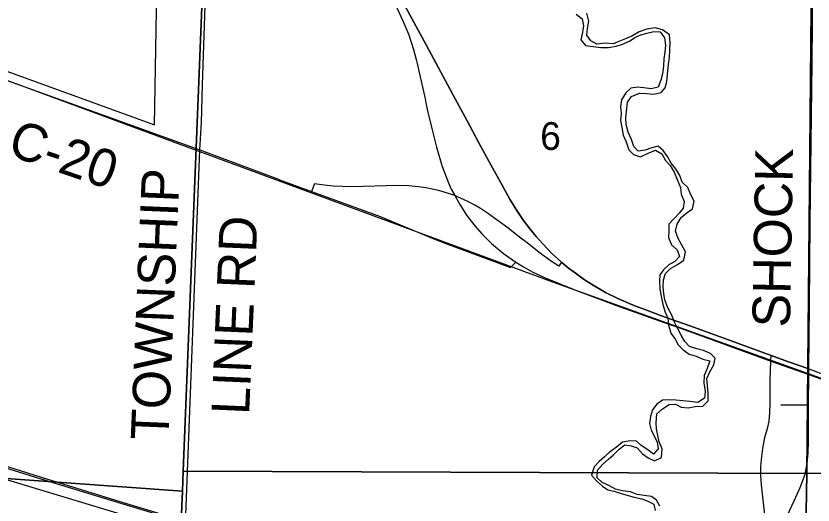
# Model space of a CAD drawing. Extents: x 0 to 34, y 0 to 22.
# Drawn here: x 25.81 to 27.011, y 18.872 to 19.609 of the extents above; entities that cross this region are included whole.
import ezdxf

# ---------------------------------------------------------------- set-up
doc = ezdxf.new("R2010")
doc.units = 0
for name, color, linetype in [('GM_X_City_Street', 7, 'Continuous'), ('GM_X_County_Road', 7, 'Continuous'), ('GM_X_County_Road_Text', 7, 'Continuous'), ('GM_X_Interchange_Ramps', 7, 'Continuous'), ('GM_X_Minor_River', 7, 'Continuous'), ('GM_X_Rail_Line', 7, 'Continuous'), ('GM_X_Section', 7, 'Continuous'), ('GM_X_Section_Text', 7, 'Continuous'), ('GM_X_State_Route', 7, 'Continuous'), ('GM_X_Township_Road', 7, 'Continuous'), ('GM_X_Township_Road_Text', 7, 'Continuous'), ('GM_X_US_Route', 7, 'Continuous')]:
    doc.layers.add(name, color=color, linetype=linetype)

msp = doc.modelspace()

# ---------------------------------------------------------------- linework, layer by layer
at = {"layer": 'GM_X_City_Street'}
msp.add_lwpolyline([(25.7608, 19.5385), (26.0181, 19.4449), (26.0246, 19.8182), (26.0322, 19.818), (26.0322, 20.0343), (26.0952, 20.0332), (26.0952, 20.0736), (25.9699, 20.3158)], dxfattribs=at)
at = {"layer": 'GM_X_County_Road'}
msp.add_line((26.0643, 18.8283), (26.0866, 19.4072), dxfattribs=at)
for points in [[(26.0866, 19.4072), (26.089, 19.4486), (26.0905, 19.5054), (26.0945, 19.6244), (26.0989, 19.7481), (26.1013, 19.8177), (26.1022, 19.82)], [(25.5658, 19.595), (25.7402, 19.5316), (26.0796, 19.4097), (26.0866, 19.4072)], [(26.0866, 19.4072), (26.2051, 19.3627), (26.2079, 19.3616)], [(26.2079, 19.3616), (26.2548, 19.3444), (26.2743, 19.3373)], [(26.2743, 19.3373), (26.3581, 19.3069), (26.4391, 19.2729)]]:
    msp.add_lwpolyline(points, dxfattribs=at)
at = {"layer": 'GM_X_Interchange_Ramps'}
for points in [[(26.5704, 19.2741), (26.5614, 19.281), (26.5508, 19.2894), (26.5291, 19.3051), (26.5214, 19.3106), (26.5095, 19.3185), (26.5008, 19.3238), (26.4916, 19.3287), (26.474, 19.337), (26.4706, 19.3385), (26.4468, 19.3457), (26.4368, 19.3481), (26.4271, 19.35), (26.4159, 19.3516), (26.4013, 19.3528), (26.3849, 19.3532), (26.3673, 19.3531), (26.3326, 19.3517), (26.3133, 19.3515), (26.3023, 19.3517), (26.2877, 19.3526), (26.2741, 19.3539), (26.2592, 19.356), (26.2548, 19.3444)], [(26.4391, 19.2729), (26.4572, 19.2658), (26.5548, 19.2296), (26.5627, 19.2378)], [(26.6317, 19.2379), (26.6274, 19.2318), (26.6167, 19.2389), (26.6, 19.2511), (26.5778, 19.2685), (26.5704, 19.2741)]]:
    msp.add_lwpolyline(points, dxfattribs=at)
at = {"layer": 'GM_X_Minor_River'}
for points in [[(26.6536, 19.6116), (26.6629, 19.6049), (26.6649, 19.5942), (26.6631, 19.5844), (26.6609, 19.5731), (26.6679, 19.5645), (26.6792, 19.5631), (26.6906, 19.5612), (26.7023, 19.5613), (26.7141, 19.5636), (26.7233, 19.5664), (26.7341, 19.571), (26.7418, 19.5765), (26.751, 19.5804), (26.7602, 19.5832), (26.7705, 19.5856), (26.7803, 19.585), (26.7869, 19.576), (26.7881, 19.565), (26.7871, 19.5544), (26.7857, 19.5446), (26.7854, 19.5332), (26.7835, 19.5215), (26.7814, 19.512), (26.7773, 19.5015), (26.7666, 19.4991), (26.7557, 19.5006), (26.7458, 19.5016), (26.7359, 19.5), (26.7285, 19.493), (26.7218, 19.4825), (26.7204, 19.4719), (26.7213, 19.462), (26.7206, 19.4514), (26.7222, 19.4408), (26.7245, 19.4293), (26.7292, 19.4193), (26.733, 19.407), (26.7401, 19.4), (26.7506, 19.3967), (26.761, 19.4017), (26.7732, 19.4067), (26.7829, 19.4011), (26.788, 19.3911), (26.7953, 19.3833), (26.8015, 19.3736), (26.8058, 19.3625), (26.8108, 19.3502), (26.8116, 19.3403), (26.8166, 19.3292), (26.8148, 19.319), (26.8086, 19.3116), (26.8012, 19.3038), (26.7933, 19.2949), (26.7931, 19.2854), (26.7928, 19.2748), (26.7974, 19.264), (26.8056, 19.2562)], [(26.8226, 19.0184), (26.8329, 19.0201), (26.8443, 19.0209), (26.8525, 19.029), (26.8524, 19.0404), (26.8516, 19.0514), (26.8507, 19.0625), (26.8552, 19.0726), (26.8612, 19.0831), (26.863, 19.0933), (26.8559, 19.0999), (26.8454, 19.1048), (26.8356, 19.1069), (26.8244, 19.1107), (26.8174, 19.1184), (26.8116, 19.1277), (26.8069, 19.1373), (26.8019, 19.1473), (26.7972, 19.1589), (26.7918, 19.1689), (26.7872, 19.1812), (26.7856, 19.1907), (26.7847, 19.2002), (26.785, 19.2112), (26.7883, 19.2206), (26.7957, 19.2284), (26.8065, 19.2345), (26.8161, 19.2407), (26.8184, 19.2536), (26.813, 19.2636), (26.8072, 19.2733), (26.8033, 19.2844), (26.8058, 19.2949), (26.8118, 19.305), (26.8207, 19.3127), (26.8289, 19.3182), (26.8314, 19.3299), (26.8264, 19.3395), (26.8221, 19.3503), (26.8136, 19.3585), (26.8097, 19.3685), (26.8036, 19.3785), (26.797, 19.3871), (26.7912, 19.3971), (26.7846, 19.406), (26.7772, 19.4127), (26.7676, 19.4103), (26.7577, 19.4067), (26.747, 19.4051), (26.7404, 19.4122), (26.7369, 19.4229), (26.7319, 19.4337), (26.7291, 19.4455), (26.7283, 19.4558), (26.7302, 19.469), (26.7312, 19.4789), (26.7371, 19.4874), (26.749, 19.4928), (26.7596, 19.4921), (26.7706, 19.4911), (26.7816, 19.4934), (26.7875, 19.5008), (26.7901, 19.5103), (26.7915, 19.5209), (26.7927, 19.5364), (26.7941, 19.5462), (26.7947, 19.5572), (26.7951, 19.5686), (26.7942, 19.5804), (26.7838, 19.5879), (26.7729, 19.5909), (26.76, 19.5893), (26.7485, 19.5851), (26.7377, 19.5785), (26.7281, 19.5746), (26.7181, 19.5703), (26.7093, 19.5668), (26.6976, 19.5682), (26.685, 19.5667), (26.6757, 19.5715), (26.6698, 19.58), (26.6709, 19.5899), (26.6727, 19.6012), (26.6696, 19.6131)], [(26.8056, 19.2562), (26.8095, 19.2462), (26.8021, 19.2388), (26.7932, 19.2338), (26.785, 19.2264), (26.7795, 19.2186), (26.7793, 19.2091), (26.7797, 19.1969), (26.7817, 19.1866), (26.784, 19.174), (26.7879, 19.1625), (26.7918, 19.1537), (26.793, 19.143), (26.7961, 19.1308), (26.8027, 19.1219), (26.8074, 19.1134), (26.8151, 19.1056), (26.824, 19.0989), (26.8346, 19.0959), (26.8443, 19.0915), (26.8549, 19.0889), (26.8508, 19.0777), (26.8467, 19.0668), (26.846, 19.0561), (26.8479, 19.0428), (26.8469, 19.0326), (26.8372, 19.026), (26.8248, 19.0279), (26.8146, 19.0289), (26.804, 19.0296), (26.7934, 19.0303), (26.7839, 19.0298), (26.775, 19.0235), (26.7687, 19.015), (26.7654, 19.0052), (26.764, 18.9946), (26.7667, 18.9847), (26.771, 18.9758), (26.7757, 18.9662), (26.777, 18.9563), (26.7703, 18.9485), (26.7617, 18.9548), (26.7517, 18.9612), (26.7447, 18.9678), (26.7352, 18.9684), (26.7234, 18.9665), (26.7145, 18.9588), (26.7036, 18.9507), (26.6962, 18.9445), (26.6881, 18.9375), (26.6807, 18.9293), (26.6769, 18.9165), (26.6843, 18.908), (26.6931, 18.9001), (26.7013, 18.8946), (26.7108, 18.8924), (26.7213, 18.8891), (26.7318, 18.8858), (26.7412, 18.8836), (26.7525, 18.881), (26.7616, 18.8777), (26.7705, 18.8729), (26.7725, 18.8634)], [(26.7754, 19.0091), (26.7839, 19.0165), (26.7936, 19.023), (26.8031, 19.0239), (26.812, 19.0191), (26.8226, 19.0184)], [(26.7799, 18.87), (26.7749, 18.8789), (26.767, 18.8844), (26.7561, 18.8859), (26.7455, 18.8873), (26.7354, 18.8914), (26.7233, 18.8932), (26.7131, 18.8958), (26.703, 18.901), (26.6929, 18.9058), (26.6852, 18.9129), (26.6858, 18.9242), (26.694, 18.9331), (26.7022, 18.9409), (26.71, 18.9475), (26.7186, 18.956), (26.7271, 18.9622), (26.7365, 18.9608), (26.7455, 18.9579), (26.7536, 18.949), (26.7622, 18.943), (26.7719, 18.9382), (26.7823, 18.9432), (26.7834, 18.9565), (26.7788, 18.9669), (26.7767, 18.9764), (26.7747, 18.9863), (26.7742, 18.9958), (26.7754, 19.0091)]]:
    msp.add_lwpolyline(points, dxfattribs=at)
at = {"layer": 'GM_X_Rail_Line'}
for points in [[(24.6857, 19.9193), (25.0148, 19.7985), (25.4772, 19.6296), (26.0332, 19.4244), (26.618, 19.2083), (27.1754, 19.0083), (27.8265, 18.7785), (28.397, 18.5695), (29.2915, 18.2251), (29.5147, 18.1387)], [(24.1704, 19.5327), (24.2425, 19.4909), (24.3878, 19.4135), (24.5787, 19.3195), (24.7175, 19.2589), (24.8405, 19.2105), (24.9746, 19.1639), (25.4423, 19.0168), (26.3104, 18.7542), (27.1506, 18.4971), (27.9899, 18.2401), (28.4862, 18.088)], [(25.1011, 19.1396), (25.1536, 19.1235), (25.2694, 19.0879), (25.2996, 19.0787), (25.3683, 19.0577), (25.4595, 19.0299), (25.6015, 18.9867), (25.8055, 18.9242), (25.847, 18.9114), (25.9704, 18.8734), (26.0653, 18.8446), (26.2947, 18.7744), (26.4597, 18.7238), (26.5651, 18.6918), (26.6458, 18.6671), (26.7252, 18.6428), (26.8299, 18.611), (26.9128, 18.5857), (26.9875, 18.5627), (27.1965, 18.4991)], [(25.4438, 19.0347), (25.4601, 19.0321), (25.6021, 18.989), (25.8062, 18.9265), (25.8477, 18.9137), (25.9711, 18.8756), (26.066, 18.8468), (26.2954, 18.7766), (26.4604, 18.726), (26.5658, 18.694), (26.6465, 18.6693), (26.6813, 18.6587), (26.7055, 18.6488)]]:
    msp.add_lwpolyline(points, dxfattribs=at)
at = {"layer": 'GM_X_Section'}
for points in [[(28.0159, 19.8585), (28.001, 18.9217), (27.0012, 18.9192), (27.0095, 19.8363), (27.044, 19.8365)], [(25.0077, 19.8483), (25.0925, 19.8455), (26.0975, 19.8234), (26.0616, 18.9227), (26.0607, 18.8928), (24.9624, 18.9716)], [(27.0095, 19.8363), (27.0012, 18.9192), (26.0616, 18.9227), (26.0975, 19.8234)], [(26.0607, 18.8928), (26.0171, 17.9156), (26.0158, 17.891), (24.9267, 17.9117), (24.9624, 18.9716)], [(27.0012, 18.9192), (26.984, 17.9172), (26.0171, 17.9156), (26.0607, 18.8928), (26.0616, 18.9227)], [(28.001, 18.9217), (27.9928, 17.9132), (26.984, 17.9172), (27.0012, 18.9192)]]:
    msp.add_lwpolyline(points, close=True, dxfattribs=at)
at = {"layer": 'GM_X_State_Route'}
for points in [[(26.6317, 19.2379), (26.6172, 19.251), (26.6032, 19.2656), (26.5934, 19.2766), (26.5842, 19.2878), (26.5743, 19.3006), (26.5641, 19.3156), (26.5541, 19.3318), (26.5394, 19.3582), (26.5252, 19.3845), (26.5072, 19.4178), (26.4892, 19.4511), (26.4714, 19.4841), (26.4568, 19.5111), (26.4422, 19.5383), (26.4245, 19.571), (26.4065, 19.6043), (26.3883, 19.6381)], [(26.9477, 19.0971), (26.8819, 19.121), (26.8317, 19.1392), (26.7824, 19.157), (26.7611, 19.1649), (26.7396, 19.1731), (26.7174, 19.1826), (26.6977, 19.1923), (26.6792, 19.203), (26.6662, 19.2114), (26.6539, 19.2201), (26.6421, 19.229), (26.6317, 19.2379)], [(27.0042, 19.0768), (26.9737, 19.0877), (26.9477, 19.0971)], [(27.0041, 19.0684), (27.0041, 19.0714), (27.0042, 19.0768)], [(26.9651, 18.8414), (26.9822, 18.8778), (26.9912, 18.8979), (26.9985, 18.9182), (27.0019, 18.9342), (27.0031, 18.9504), (27.0037, 18.9675), (27.0038, 19.022), (27.0041, 19.0684)]]:
    msp.add_lwpolyline(points, dxfattribs=at)
at = {"layer": 'GM_X_Township_Road'}
msp.add_line((27.0038, 19.022), (26.9619, 19.0221), dxfattribs=at)
for points in [[(27.0042, 19.0768), (27.005, 19.173), (27.0061, 19.2969), (27.0091, 19.5392), (27.0117, 19.8339)], [(26.9438, 18.7976), (26.9401, 18.8386), (26.933, 18.9019), (26.9318, 18.9164), (26.9321, 18.9296), (26.9332, 18.9447), (26.9348, 18.9571), (26.938, 18.9733), (26.9426, 18.9888), (26.9445, 18.9983), (26.9455, 19.0107), (26.946, 19.0253), (26.9461, 19.0601), (26.9472, 19.0885), (26.9477, 19.0971)]]:
    msp.add_lwpolyline(points, dxfattribs=at)
at = {"layer": 'GM_X_US_Route'}
for points in [[(26.3883, 19.6381), (26.4065, 19.6043), (26.4245, 19.571), (26.4422, 19.5383), (26.4568, 19.5111), (26.4714, 19.4841), (26.4892, 19.4511), (26.5072, 19.4178), (26.5252, 19.3845), (26.5394, 19.3582), (26.5541, 19.3318), (26.5641, 19.3156), (26.5743, 19.3006), (26.5842, 19.2878), (26.5934, 19.2766), (26.6032, 19.2656), (26.6172, 19.251), (26.6317, 19.2379)], [(26.3777, 19.6323), (26.3839, 19.6203), (26.3926, 19.6017), (26.4013, 19.5806), (26.4087, 19.5583), (26.4127, 19.5433), (26.4141, 19.5374)], [(26.4141, 19.5374), (26.4161, 19.5285), (26.4225, 19.4996), (26.426, 19.484), (26.4272, 19.478)], [(26.4272, 19.478), (26.4297, 19.466), (26.4357, 19.4412), (26.4432, 19.4111), (26.4518, 19.3818), (26.4614, 19.3573), (26.4655, 19.3479), (26.4706, 19.3385), (26.4781, 19.3245), (26.4896, 19.3071), (26.5014, 19.292), (26.5114, 19.2807), (26.5261, 19.2661), (26.5439, 19.2509), (26.5627, 19.2378)], [(26.5627, 19.2378), (26.5742, 19.2306), (26.5883, 19.2229), (26.6051, 19.2151), (26.607, 19.2143)], [(26.6317, 19.2379), (26.6421, 19.229), (26.6539, 19.2201), (26.6662, 19.2114), (26.6792, 19.203), (26.6977, 19.1923), (26.7174, 19.1826), (26.7396, 19.1731), (26.7611, 19.1649), (26.7824, 19.157), (26.8317, 19.1392), (26.8819, 19.121), (26.9477, 19.0971)], [(26.607, 19.2143), (26.6564, 19.194), (26.692, 19.1808), (26.7129, 19.1732), (26.7863, 19.1468)], [(26.7863, 19.1468), (26.8121, 19.1376), (26.9472, 19.0885), (27.0041, 19.0684), (27.0497, 19.0517)], [(26.9477, 19.0971), (26.9737, 19.0877), (27.0042, 19.0768)], [(27.0042, 19.0768), (27.0338, 19.0659), (27.0763, 19.0506), (27.1619, 19.0197), (27.2046, 19.0042), (27.2509, 18.9877), (27.2902, 18.9738), (27.3459, 18.9544), (27.4319, 18.924), (27.4616, 18.9134), (27.4954, 18.9016)]]:
    msp.add_lwpolyline(points, dxfattribs=at)

# ---------------------------------------------------------------- texts
at = {"layer": 'GM_X_County_Road_Text'}
for s, rotation, p in [('C-20', 341.1304, (25.7946, 19.4002)), ('TOWNSHIP', 87.6083, (26.0392, 18.9687)), ('LINE RD', 87.541, (26.1608, 19.007))]:
    msp.add_text(s, height=0.05682, rotation=rotation, dxfattribs=at).set_placement(p)
at = {"layer": 'GM_X_Section_Text'}
msp.add_text('6', height=0.0419, rotation=0, dxfattribs=at).set_placement((26.5994, 19.407))
at = {"layer": 'GM_X_Township_Road_Text'}
msp.add_text('SHOCK', height=0.05682, rotation=88.984, dxfattribs=at).set_placement((26.9758, 19.139))

doc.saveas('drawing.dxf')
